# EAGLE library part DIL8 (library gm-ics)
Dual In Line
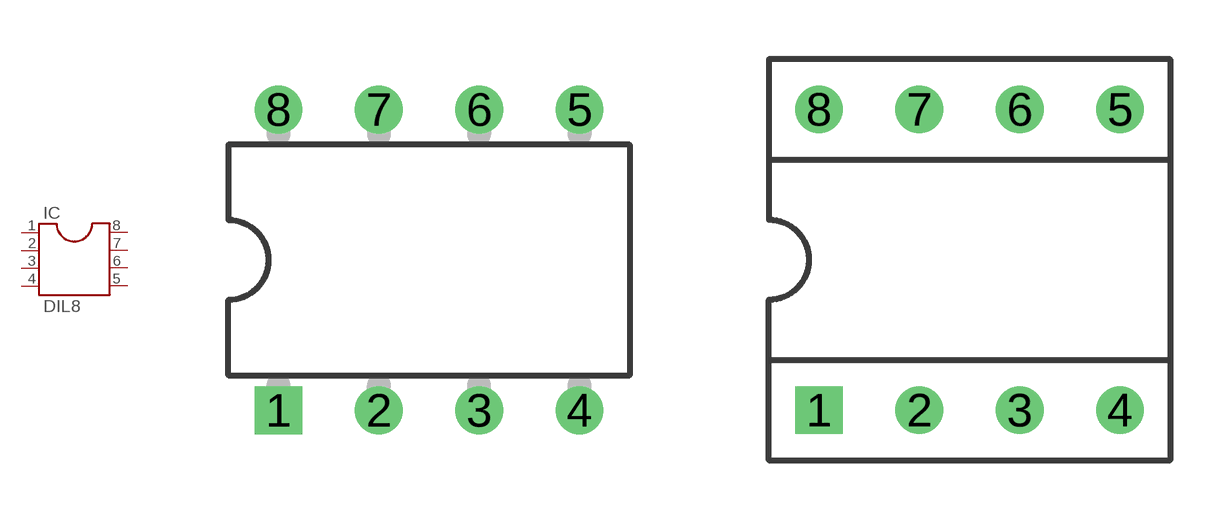
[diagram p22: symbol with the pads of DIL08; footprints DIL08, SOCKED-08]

Designator prefix IC

## DIL8  [DIL08]
1  1  pas
2  2  pas
3  3  pas
4  4  pas
5  5  pas
6  6  pas
7  7  pas
8  8  pas

## DIL8S  [SOCKED-08]
Pads as for DIL08

## DIL8STRCH  [MN3005]
Pads as for DIL08

## Footprint DIL08 (pad centres in mm)
Dual In Line Package
drill 0.7 square: 1 -3.81,-3.81
drill 0.7 round: 2 -1.27,-3.81; 3 1.27,-3.81; 4 3.81,-3.81; 5 3.81,3.81; 6 1.27,3.81; 7 -1.27,3.81; 8 -3.81,3.81

## Footprint SOCKED-08 (pad centres in mm)
Dual In Line Socket
drill 0.7 square: 1 -3.81,-3.81
drill 0.7 round: 2 -1.27,-3.81; 3 1.27,-3.81; 4 3.81,-3.81; 5 3.81,3.81; 6 1.27,3.81; 7 -1.27,3.81; 8 -3.81,3.81

## Footprint MN3005 (pad centres in mm)
drill 0.7 square: 1 -8.89,-3.81
drill 0.7 round: 2 -6.35,-3.81; 3 6.35,-3.81; 4 8.89,-3.81; 5 8.89,3.81; 6 6.35,3.81; 7 -6.35,3.81; 8 -8.89,3.81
